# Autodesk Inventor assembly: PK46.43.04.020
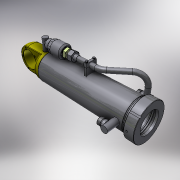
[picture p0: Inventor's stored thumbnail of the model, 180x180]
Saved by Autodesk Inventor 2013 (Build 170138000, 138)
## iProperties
Shininess: 64.0
Length Units: 11269
Angle Units: 11279
Time Units: 11290
Mass Units: 11283
Length Display Precision: 3
Angle Display Precision: 2
Compacted: True
Created: 2004-11
Part Number: PK46.43.04.020
Document SubType Name: Assembly
Designer: ELarisa
Manufacturer: Standard
Standards Organization: Custom
Density: 0.0
Volumn: 0.0
Area: 0.0
PropertySet Name: Model Information
Control State: 0
Master: False
Checked Out: False
Author: ELarisa
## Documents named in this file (12)
- C:\Product Design Suite 2013 Test Drive\Dynamic Simulation\Workspace\Assy, Chassis, Front\PK46.43.04.020.iam
- C:\Product Design Suite 2013 Test Drive\Dynamic Simulation\Workspace\Assy, Chassis, Front\PK46.43.02.002.ipt
- C:\Product Design Suite 2013 Test Drive\Dynamic Simulation\Workspace\Assy, Chassis, Front\PK46.43.02.007.ipt
- C:\Product Design Suite 2013 Test Drive\Dynamic Simulation\Workspace\Assy, Chassis, Front\PK46.43.02.015.ipt
- C:\Product Design Suite 2013 Test Drive\Dynamic Simulation\Workspace\Assy, Chassis, Front\PK46.43.02.006.ipt
- C:\Product Design Suite 2013 Test Drive\Dynamic Simulation\Workspace\Assy, Chassis, Front\027.01.01.550.iam
- C:\Product Design Suite 2013 Test Drive\Dynamic Simulation\Workspace\Assy, Chassis, Front\PK46.43.02.040.iam
- C:\Product Design Suite 2013 Test Drive\Dynamic Simulation\Workspace\Assy, Chassis, Front\PK46.43.02.016.ipt
- C:\Product Design Suite 2013 Test Drive\Dynamic Simulation\Workspace\Assy, Chassis, Front\62900A.ipt
- C:\Product Design Suite 2013 Test Drive\Dynamic Simulation\Workspace\Assy, Chassis, Front\8.65G.019.ipt
- C:\Product Design Suite 2013 Test Drive\Dynamic Simulation\Workspace\Assy, Chassis, Front\PK46.43.00.008.ipt
- C:\Product Design Suite 2013 Test Drive\Dynamic Simulation\Workspace\Assy, Chassis, Front\M8-6gx50.58.019(S13).ipt
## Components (14 placed, 11 different names)
1. PK46.43.02.002:1 — Вставка:1, Угол:1, Угол:3, Вставка:16, Вставка:19
2. PK46.43.02.007:1 — Вставка:1, Угол:1, Угол:2, Вставка:4
3. PK46.43.02.015:1 — Угол:2, Вставка:5, Вставка:8
4. 027.01.01.550:1 [sub-assembly] — Вставка:4, Угол:3, Вставка:13, Угол:4
5. PK46.43.02.040:1 [sub-assembly] — Вставка:15
6. PK46.43.02.016:1 — Вставка:5, Вставка:6, Вставка:7, Вставка:8
7. 8.65G.019:1 — Вставка:6, Вставка:10
8. 8.65G.019:2 — Вставка:7, Вставка:9
9. M8-6gx50.58.019(S13):1 — Вставка:10
10. M8-6gx50.58.019(S13):2 — Вставка:9
11. 62900A:1 — Вставка:13, Вставка:14
12. PK46.43.00.008:1 — Вставка:14, Вставка:15
13. 027.01.01.550:2 [sub-assembly] — Вставка:16, Угол:4
14. PK46.43.02.006:1 — Вставка:19
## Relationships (17: Insert 13, Angle 4)
- Вставка:1 [Insert]: PK46.43.02.002:1 ↔ PK46.43.02.007:1
- Угол:1 [Angle]: PK46.43.02.002:1 ↔ PK46.43.02.007:1
- Угол:2 [Angle]: PK46.43.02.007:1 ↔ PK46.43.02.015:1
- Вставка:4 [Insert]: PK46.43.02.007:1 ↔ 027.01.01.550:1
- Угол:3 [Angle]: PK46.43.02.002:1 ↔ 027.01.01.550:1
- Вставка:5 [Insert]: PK46.43.02.015:1 ↔ PK46.43.02.016:1
- Вставка:6 [Insert]: PK46.43.02.016:1 ↔ 8.65G.019:1
- Вставка:7 [Insert]: PK46.43.02.016:1 ↔ 8.65G.019:2
- Вставка:8 [Insert]: PK46.43.02.015:1 ↔ PK46.43.02.016:1
- Вставка:9 [Insert]: 8.65G.019:2 ↔ M8-6gx50.58.019(S13):2
- Вставка:10 [Insert]: 8.65G.019:1 ↔ M8-6gx50.58.019(S13):1
- Вставка:13 [Insert]: 027.01.01.550:1 ↔ 62900A:1
- Вставка:14 [Insert]: 62900A:1 ↔ PK46.43.00.008:1
- Вставка:15 [Insert]: PK46.43.02.040:1 ↔ PK46.43.00.008:1
- Вставка:16 [Insert]: PK46.43.02.002:1 ↔ 027.01.01.550:2
- Угол:4 [Angle]: 027.01.01.550:1 ↔ 027.01.01.550:2
- Вставка:19 [Insert]: PK46.43.02.002:1 ↔ PK46.43.02.006:1
